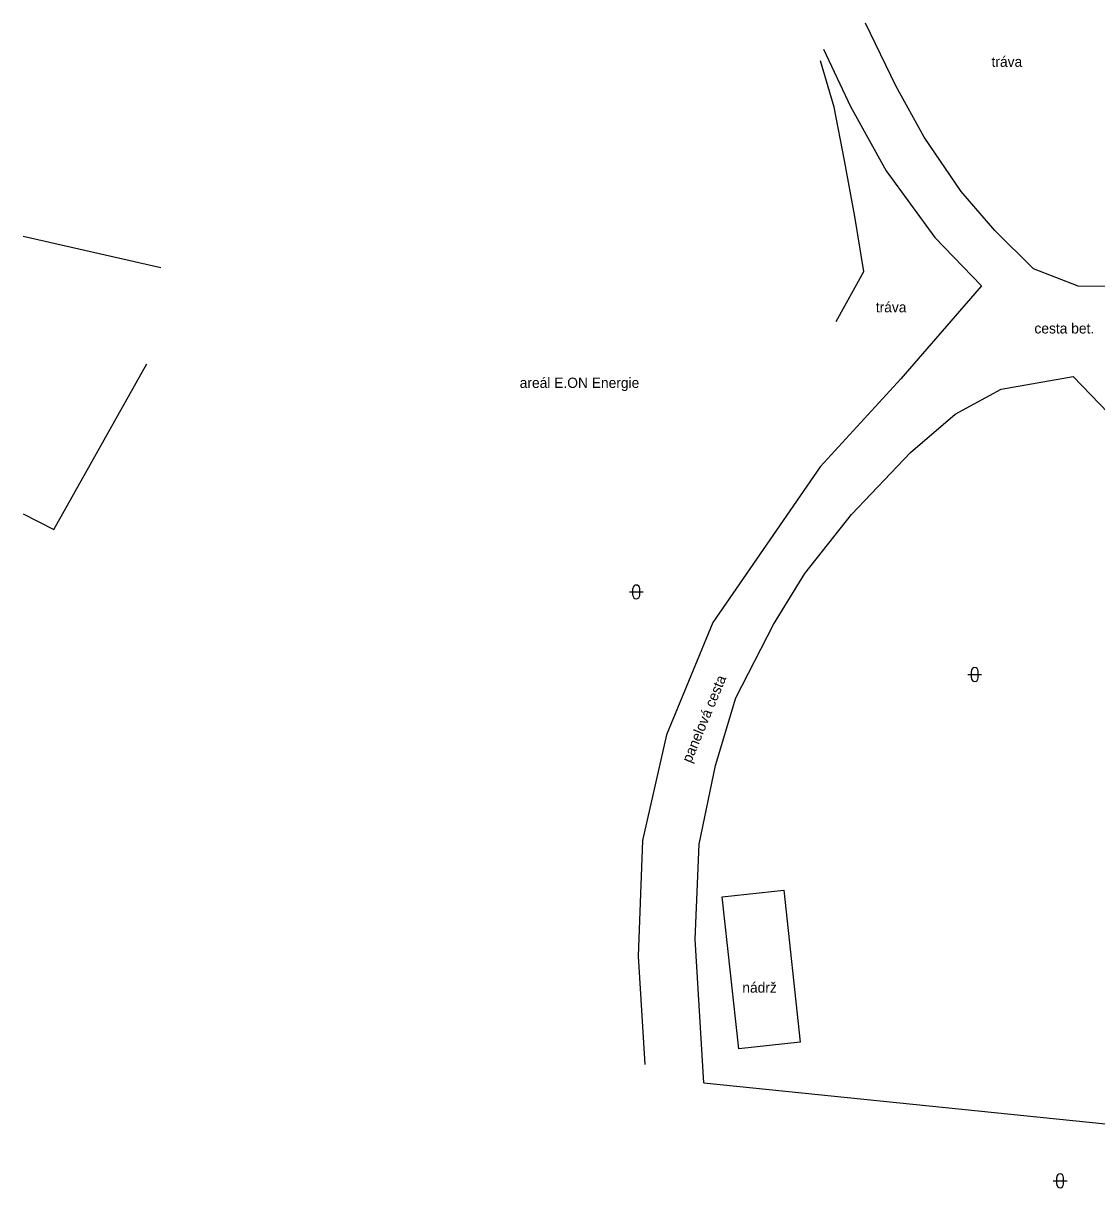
# Model space of a CAD drawing. Extents: x -762500 to -761246, y -1152986 to -1152252.
# Drawn here: x -762500 to -762421.9, y -1152842.1 to -1152757.3 of the extents above; entities that cross this region are included whole.
import ezdxf

# ---------------------------------------------------------------- set-up
doc = ezdxf.new("R2010")
doc.units = 0
for name, color, linetype in [('Vrstva 10', 7, 'Continuous'), ('Vrstva 11', 7, 'Continuous'), ('Vrstva 14', 7, 'Continuous'), ('Vrstva 3', 7, 'Continuous'), ('Vrstva 9', 7, 'Continuous')]:
    doc.layers.add(name, color=color, linetype=linetype)

msp = doc.modelspace()

# ---------------------------------------------------------------- linework, layer by layer
at = {"layer": 'Vrstva 10'}
msp.add_line((-762430.3, -1152776.43), (-762431.59, -1152777.91), dxfattribs=at)
for points in [[(-762429.34, -1152772.4), (-762431.79, -1152769.58), (-762434.47, -1152765.62), (-762436.54, -1152761.88), (-762438.75, -1152757.33)], [(-762441.8, -1152759.21), (-762439.82, -1152763.39), (-762437.24, -1152768.06), (-762433.69, -1152772.91), (-762430.3, -1152776.43)], [(-762408.57, -1152765.72), (-762412.44, -1152771.55), (-762417.46, -1152775.73), (-762420.65, -1152776.48), (-762423.27, -1152776.45), (-762426.51, -1152775.19), (-762429.34, -1152772.4)], [(-762431.59, -1152777.91), (-762436.17, -1152783.19), (-762442.04, -1152789.59), (-762449.85, -1152800.92), (-762453.22, -1152809.09), (-762454.95, -1152816.78), (-762455.27, -1152825.2), (-762454.8, -1152833.08)], [(-762450.5, -1152834.43), (-762451.13, -1152823.97), (-762450.84, -1152817.06), (-762449.64, -1152811.32), (-762448.18, -1152806.41), (-762445.43, -1152801.07), (-762443.14, -1152797.36), (-762439.75, -1152793.07), (-762435.46, -1152788.55), (-762432.22, -1152785.76), (-762428.86, -1152783.96), (-762423.63, -1152783.04), (-762418.52, -1152788.33), (-762407.11, -1152799.74), (-762391.21, -1152815.08), (-762393.27, -1152818.47), (-762395.24, -1152824.71), (-762393.61, -1152825.21), (-762394.31, -1152826.99), (-762391.38, -1152828.93), (-762393.77, -1152835.64)]]:
    msp.add_lwpolyline(points, dxfattribs=at)
at = {"layer": 'Vrstva 11'}
msp.add_lwpolyline([(-762489.99, -1152775.12), (-762500, -1152772.85)], dxfattribs=at)
at = {"layer": 'Vrstva 3'}
for p, q in [((-762455.66, -1152798.95), (-762455.66, -1152798.45)), ((-762455.16, -1152798.95), (-762455.16, -1152798.45)), ((-762455.91, -1152798.7), (-762454.91, -1152798.7)), ((-762431.04, -1152804.96), (-762431.04, -1152804.46)), ((-762430.54, -1152804.96), (-762430.54, -1152804.46)), ((-762431.29, -1152804.71), (-762430.29, -1152804.71)), ((-762425.08, -1152841.55), (-762424.08, -1152841.55)), ((-762424.83, -1152841.8), (-762424.83, -1152841.3)), ((-762424.33, -1152841.8), (-762424.33, -1152841.3))]:
    msp.add_line(p, q, dxfattribs=at)
for centre, start, end in [((-762455.41, -1152798.45), 0, 179.99999), ((-762455.41, -1152798.95), 179.99999, 359.99999), ((-762430.79, -1152804.46), 0, 179.99999), ((-762430.79, -1152804.96), 179.99999, 359.99999), ((-762424.58, -1152841.3), 0, 179.99999), ((-762424.58, -1152841.8), 179.99999, 359.99999)]:
    msp.add_arc(centre, 0.25, start, end, dxfattribs=at)
at = {"layer": 'Vrstva 9'}
for points in [[(-762440.88, -1152779.02), (-762438.86, -1152775.4), (-762439.51, -1152771.38), (-762440.26, -1152767.31), (-762441.02, -1152763.43), (-762442.01, -1152760.07)], [(-762500, -1152793.03), (-762497.77, -1152794.16), (-762491.02, -1152782.1)], [(-762443.48, -1152831.45), (-762447.96, -1152831.94), (-762449.17, -1152820.88), (-762444.69, -1152820.39), (-762443.48, -1152831.45)], [(-762450.5, -1152834.43), (-762418.9, -1152837.64), (-762398.57, -1152839.53)]]:
    msp.add_lwpolyline(points, dxfattribs=at)

# ---------------------------------------------------------------- texts
at = {"layer": 'Vrstva 14'}
for s, p in [('tráva', (-762429.57, -1152760.5)), ('tráva', (-762437.99, -1152778.36)), ('cesta bet.', (-762426.45, -1152779.9)), ('areál E.ON Energie', (-762463.89, -1152783.86)), ('nádrž', (-762447.7, -1152827.86))]:
    msp.add_text(s, height=0.75, dxfattribs=at).set_placement(p)
msp.add_text('panelová cesta', height=0.75, rotation=67.49954, dxfattribs=at).set_placement((-762451.43, -1152811.19))

doc.saveas('drawing.dxf')
